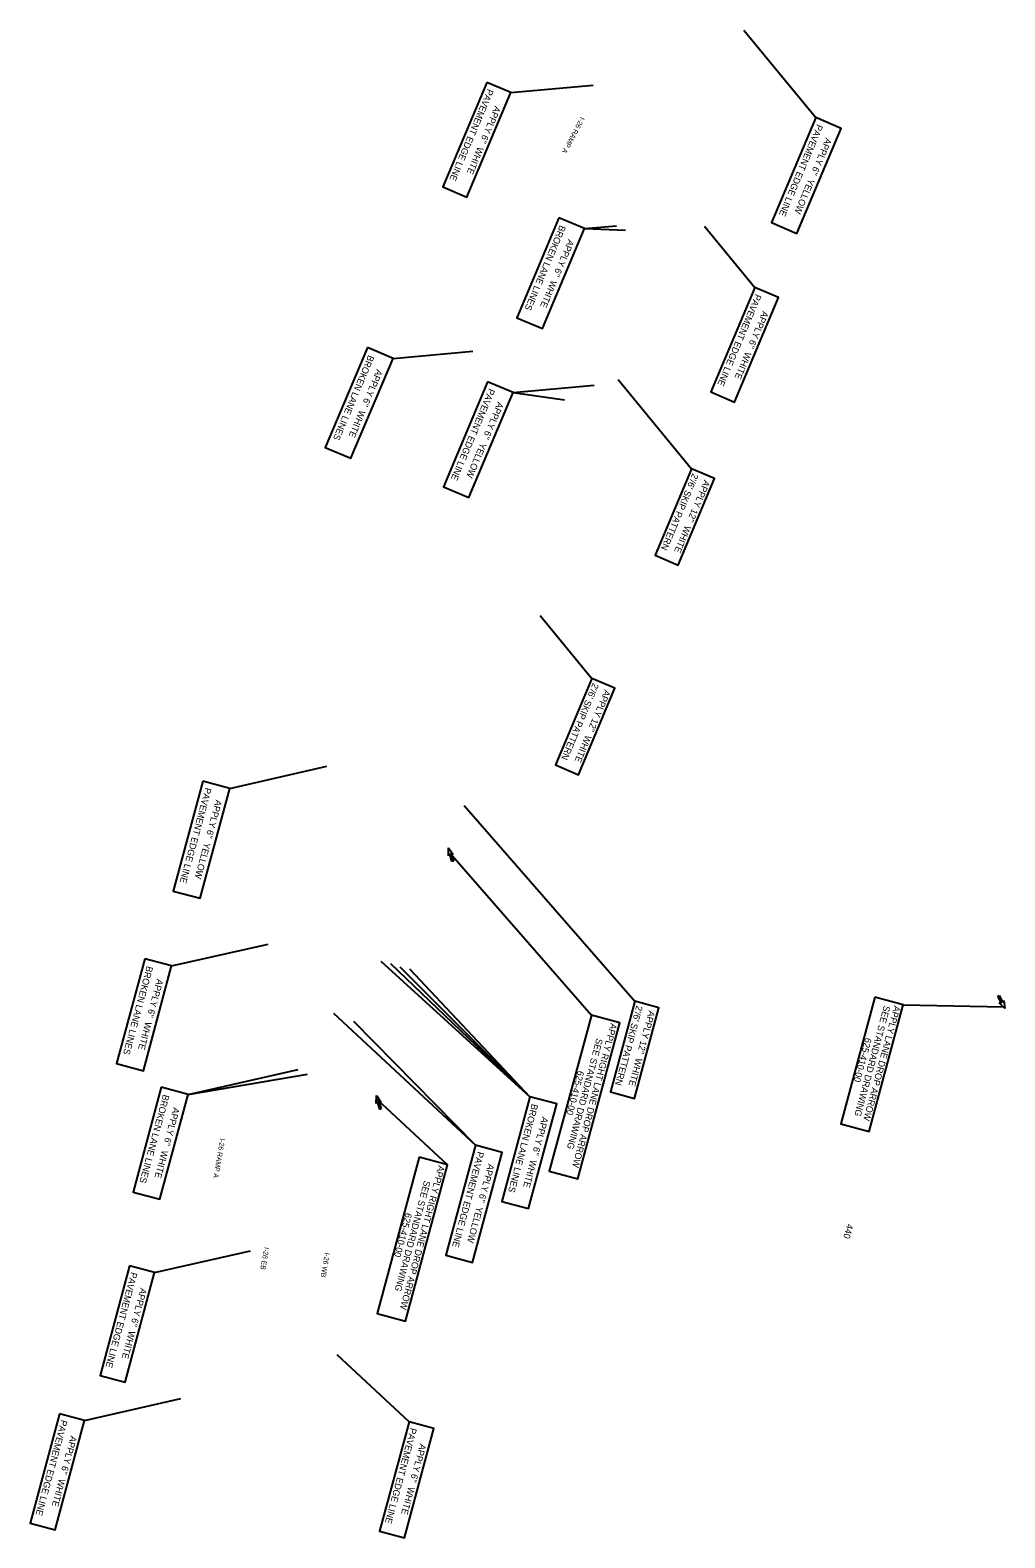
# Model space of a CAD drawing. Extents: x 1966013 to 1974896, y 789499 to 804826.
# Drawn here: x 1966135 to 1967310, y 791111 to 792930 of the extents above; entities that cross this region are included whole.
import ezdxf

# ---------------------------------------------------------------- set-up
doc = ezdxf.new("R2010")
doc.units = 0
for name, color, linetype in [('RD_EX_H2O_BlueLn', 7, 'Continuous'), ('RD_PD_Final_Cl', 7, 'Continuous'), ('RD_PD_MedBWall', 7, 'Continuous'), ('RD_PD_PaveShd', 7, 'Continuous')]:
    doc.layers.add(name, color=color, linetype=linetype)

msp = doc.modelspace()

# ---------------------------------------------------------------- linework, layer by layer
at = {"layer": 'RD_EX_H2O_BlueLn'}
for p, q in [((1966995.1, 792929.5), (1967081.6, 792824.1)), ((1966714, 792854.3), (1966813.4, 792863.2)), ((1966803, 792690.3), (1966841.5, 792693.7)), ((1966803, 792690.3), (1966852.3, 792688.5)), ((1966947.5, 792693.1), (1967008.1, 792619.1)), ((1966572.1, 792533.7), (1966668.3, 792542.4)), ((1966717, 792492.6), (1966814.6, 792501.4)), ((1966843.6, 792508.4), (1966932, 792400.6)), ((1966717, 792492.6), (1966779, 792483.9)), ((1966749.6, 792223.7), (1966811.9, 792147.8)), ((1966375.3, 792015.2), (1966492.5, 792041.9)), ((1966657.8, 791994.6), (1966863.5, 791758.6)), ((1966638.9, 791933.9), (1966639.1, 791943.5)), ((1966639.1, 791943.5), (1966644.6, 791935.6)), ((1966641, 791937), (1966811.2, 791741.7)), ((1966644.6, 791935.6), (1966642.1, 791936.7)), ((1966642.1, 791936.7), (1966644.9, 791927.4)), ((1966640.4, 791936.1), (1966638.9, 791933.9)), ((1966643.2, 791926.9), (1966640.4, 791936.1)), ((1966644.9, 791927.4), (1966643.2, 791926.9)), ((1966305.3, 791801), (1966421.8, 791827.5)), ((1966557.4, 791807), (1966737.2, 791643.4)), ((1966569, 791804.1), (1966737.2, 791643.4)), ((1966580.3, 791799.8), (1966737.2, 791643.4)), ((1966592.1, 791797.5), (1966737.2, 791643.4)), ((1967301.2, 791764.8), (1967302.8, 791765.6)), ((1967305.5, 791756.1), (1967301.2, 791764.8)), ((1967302.8, 791765.6), (1967307.1, 791756.9)), ((1967309.6, 791749.9), (1967302.9, 791756.7)), ((1967302.9, 791756.7), (1967305.5, 791756.1)), ((1967307.1, 791756.9), (1967308.2, 791759.3)), ((1967308.2, 791759.3), (1967309.6, 791749.9)), ((1966500.3, 791744.3), (1966671.5, 791584.9)), ((1967187.2, 791754.2), (1967308.2, 791751.6)), ((1966524.6, 791734.6), (1966671.5, 791584.9)), ((1966325, 791646), (1966457.6, 791676.3)), ((1966325, 791646), (1966469.2, 791670.5)), ((1966551.9, 791635.2), (1966552.1, 791644.7)), ((1966553.3, 791637.4), (1966551.9, 791635.2)), ((1966552.1, 791644.7), (1966557.5, 791636.9)), ((1966553.2, 791639.9), (1966637.9, 791561.1)), ((1966556.1, 791628.1), (1966553.3, 791637.4)), ((1966557.5, 791636.9), (1966555.1, 791637.9)), ((1966555.1, 791637.9), (1966557.9, 791628.6)), ((1966557.9, 791628.6), (1966556.1, 791628.1)), ((1966284.6, 791431.2), (1966400.2, 791457.6)), ((1966504.2, 791332.7), (1966591.4, 791251.5)), ((1966200.4, 791253), (1966316.5, 791279.5))]:
    msp.add_line(p, q, dxfattribs=at)
for points in [[(1966685.3, 792866.4), (1966632.2, 792740.4), (1966660.9, 792728.3), (1966714, 792854.3)], [(1967081.6, 792824.1), (1967028.2, 792697.5), (1967059, 792684.5), (1967112.4, 792811.1)], [(1966772.1, 792703.3), (1966721.3, 792582.7), (1966752.1, 792569.7), (1966803, 792690.3)], [(1967008.1, 792619.1), (1966955, 792493.2), (1966983.8, 792481), (1967036.9, 792607)], [(1966541.2, 792546.7), (1966490.4, 792426.2), (1966521.3, 792413.2), (1966572.1, 792533.7)], [(1966686.1, 792505.6), (1966632.8, 792379), (1966663.6, 792366), (1966717, 792492.6)], [(1966932, 792400.6), (1966887.9, 792296.3), (1966915.7, 792284.5), (1966959.7, 792388.9)], [(1966811.9, 792147.8), (1966767.8, 792043.4), (1966795.6, 792031.7), (1966839.6, 792136.1)], [(1966343, 792023.9), (1966307.3, 791891.3), (1966339.6, 791882.6), (1966375.3, 792015.2)], [(1966273, 791809.7), (1966239, 791683.3), (1966271.3, 791674.6), (1966305.3, 791801)], [(1966863.5, 791758.6), (1966834.1, 791649.2), (1966863.2, 791641.4), (1966892.6, 791750.7)], [(1967152.9, 791763.4), (1967111.8, 791610.7), (1967146.1, 791601.5), (1967187.2, 791754.2)], [(1966811.2, 791741.7), (1966760.5, 791553.4), (1966794.8, 791544.2), (1966845.5, 791732.5)], [(1966292.7, 791654.7), (1966258.7, 791528.4), (1966291.1, 791519.7), (1966325, 791646)], [(1966737.2, 791643.4), (1966703.2, 791517.1), (1966735.5, 791508.4), (1966769.5, 791634.7)], [(1966671.5, 791584.9), (1966635.8, 791452.3), (1966668.1, 791443.6), (1966703.8, 791576.2)], [(1966603.6, 791570.3), (1966552.9, 791382), (1966587.2, 791372.8), (1966637.9, 791561.1)], [(1966254.6, 791439.3), (1966219, 791307.3), (1966249.1, 791299.2), (1966284.6, 791431.2)], [(1966170.3, 791261.1), (1966134.7, 791129.1), (1966164.8, 791121), (1966200.4, 791253)], [(1966591.4, 791251.5), (1966555.8, 791119.5), (1966585.9, 791111.4), (1966621.4, 791243.4)]]:
    msp.add_lwpolyline(points, close=True, dxfattribs=at)

# ---------------------------------------------------------------- texts
for s, height, rotation, p in [('PAVEMENT EDGE LINE', 8, 247.1375, (1966686.2, 792859.3)), ("APPLY 6''  WHITE", 8, 247.1375, (1966694.9, 792838.7)), ('PAVEMENT EDGE LINE', 8, 247.1375, (1967083.3, 792816.6)), ("APPLY 6''  YELLOW", 8, 247.1375, (1967093.8, 792800.3)), ('BROKEN LANE LINES', 8, 247.1375, (1966773.3, 792694.9)), ("APPLY 6''  WHITE", 8, 247.1375, (1966783.4, 792677.8)), ('PAVEMENT EDGE LINE', 8, 247.1375, (1967009.1, 792612)), ("APPLY 6''  WHITE", 8, 247.1375, (1967017.7, 792591.5)), ('BROKEN LANE LINES', 8, 247.1375, (1966542.4, 792538.3)), ("APPLY 6''  WHITE", 8, 247.1375, (1966552.5, 792521.2)), ('PAVEMENT EDGE LINE', 8, 247.1375, (1966687.9, 792498.1)), ("APPLY 6''  YELLOW", 8, 247.1375, (1966698.4, 792481.8)), ("2'/6' SKIP PATTERN", 7.999, 247.1377, (1966933.3, 792395.7)), ("APPLY 12''  WHITE", 7.999, 247.1377, (1966947.3, 792387.6)), ("2'/6' SKIP PATTERN", 7.999, 247.1377, (1966813.2, 792142.9)), ("APPLY 12''  WHITE", 7.999, 247.1377, (1966827.2, 792134.8)), ('PAVEMENT EDGE LINE', 8, 254.9393, (1966345.8, 792016.7)), ("APPLY 6''  YELLOW", 8, 254.9393, (1966358.4, 792002)), ('BROKEN LANE LINES', 8, 254.9393, (1966275.3, 791801.5)), ("APPLY 6''  WHITE", 8, 254.9393, (1966287.6, 791785.9)), ("2'/6' SKIP PATTERN", 7.999, 254.9395, (1966865.5, 791753.9)), ("APPLY 12''  WHITE", 7.999, 254.9395, (1966880.4, 791747.8)), ('SEE STANDARD DRAWING', 8, 254.9393, (1967163.9, 791753.9)), ('APPLY LANE DROP ARROW', 8, 254.9393, (1967176.1, 791753.8)), ('APPLY RIGHT LANE DROP ARROW', 8, 254.9393, (1966834.5, 791732.5)), ('SEE STANDARD DRAWING', 8, 254.9393, (1966817.4, 791714.3)), ('625-410-00 ', 7.999, 254.9393, (1967141.5, 791715)), ('625-410-00 ', 7.999, 254.9393, (1966795, 791675.3)), ('BROKEN LANE LINES', 8, 254.9393, (1966295, 791646.6)), ("APPLY 6''  WHITE", 8, 254.9393, (1966307.4, 791631)), ('BROKEN LANE LINES', 8, 254.9393, (1966739.4, 791635.3)), ("APPLY 6''  WHITE", 8, 254.9393, (1966751.8, 791619.7)), ('PAVEMENT EDGE LINE', 8, 254.9393, (1966674.2, 791577.7)), ('APPLY RIGHT LANE DROP ARROW', 8, 254.9393, (1966626.9, 791561.1)), ("APPLY 6''  YELLOW", 8, 254.9393, (1966686.8, 791563)), ('SEE STANDARD DRAWING', 8, 254.9393, (1966609.8, 791542.9)), ('625-410-00 ', 7.999, 254.9393, (1966587.4, 791503.9)), ('PAVEMENT EDGE LINE', 8, 254.9393, (1966256.4, 791432.4)), ("APPLY 6''  WHITE", 8, 254.9393, (1966267.8, 791413.2)), ('PAVEMENT EDGE LINE', 8, 254.9393, (1966172.1, 791254.2)), ("APPLY 6''  WHITE", 8, 254.9393, (1966183.5, 791235)), ('PAVEMENT EDGE LINE', 8, 254.9393, (1966593.2, 791244.6)), ("APPLY 6''  WHITE", 8, 254.9393, (1966604.6, 791225.4))]:
    msp.add_text(s, height=height, rotation=rotation, dxfattribs=at).set_placement(p)
at = {"layer": 'RD_PD_Final_Cl'}
msp.add_text('I-26 RAMP A', height=6, rotation=259.7492, dxfattribs=at).set_placement((1966363.9, 791593.5))
at = {"layer": 'RD_PD_MedBWall'}
for s, rotation, p in [('I-26 RAMP A', 241.8074, (1966798.3, 792825.5)), ('I-26 EB', 259.6156, (1966417.1, 791462.4)), ('I-26 WB', 260.5935, (1966490, 791455.7))]:
    msp.add_text(s, height=6, rotation=rotation, dxfattribs=at).set_placement(p)
at = {"layer": 'RD_PD_PaveShd'}
msp.add_text('440', height=8, rotation=254.8308, dxfattribs=at).set_placement((1967119.5, 791490.6))

doc.saveas('drawing.dxf')
